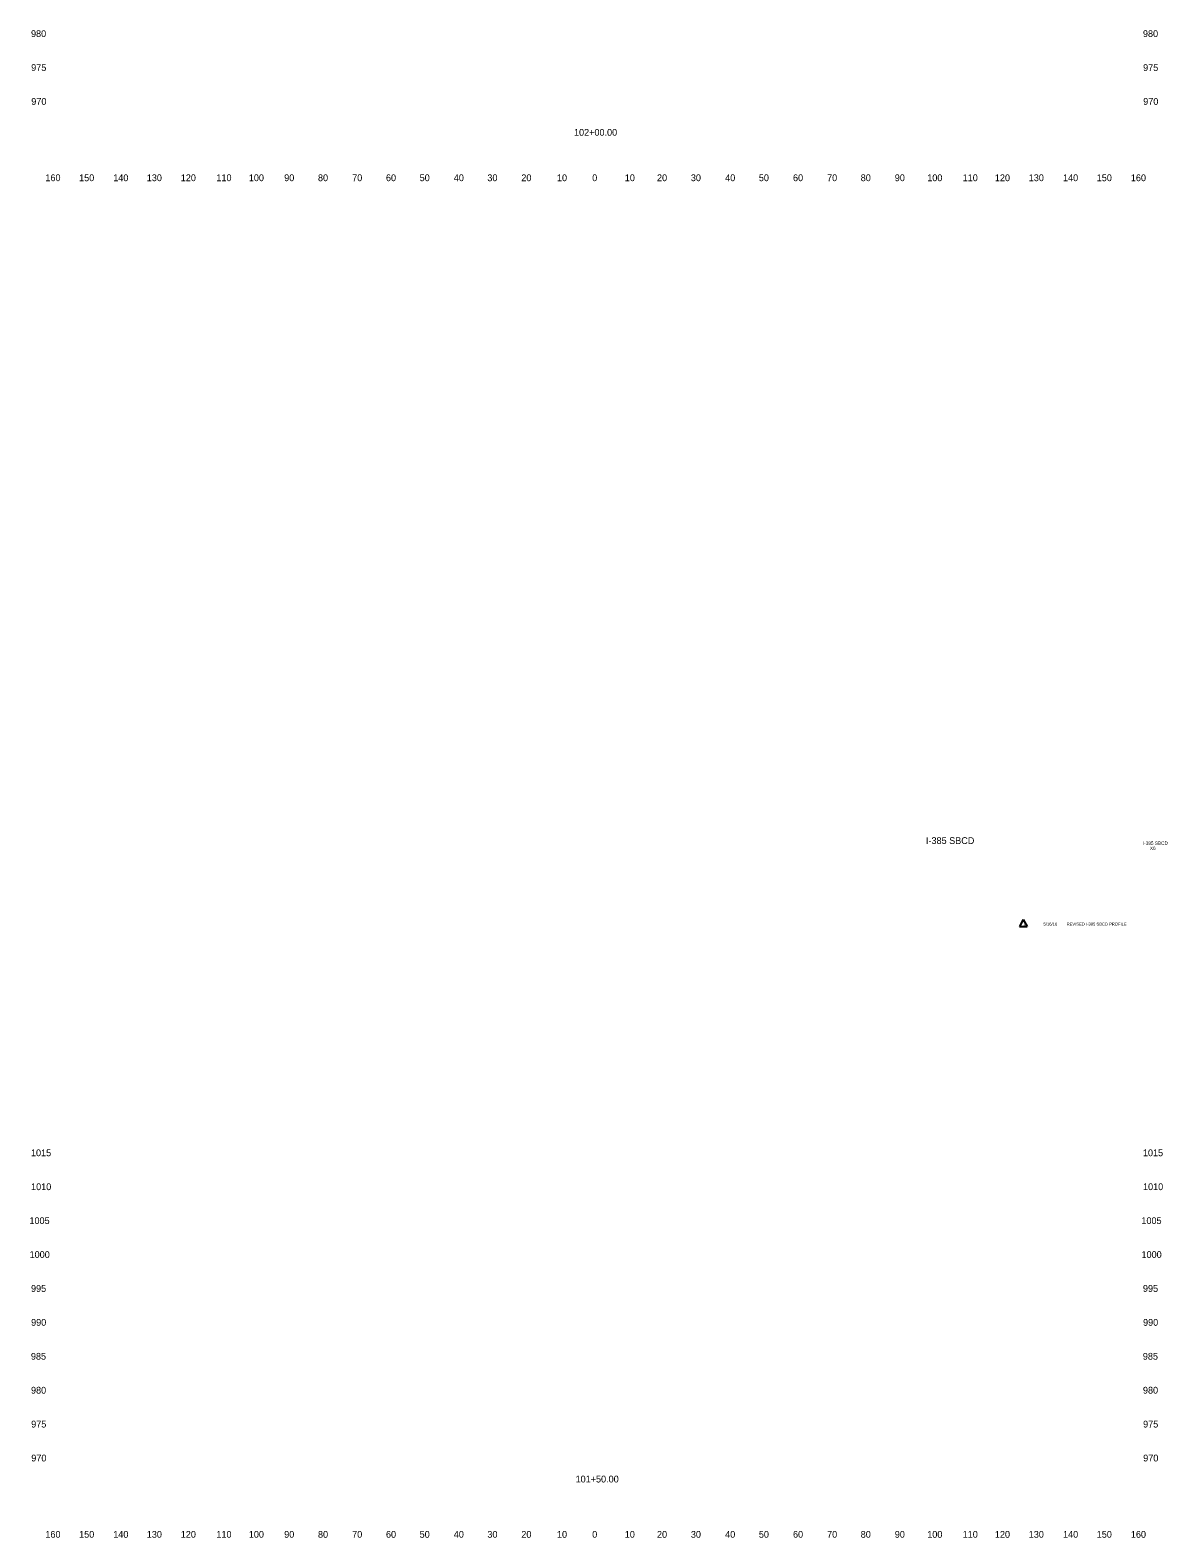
# Model space of a CAD drawing. Extents: x 4994 to 6876, y 4997 to 8804.
# Drawn here: x 4993.6 to 5328.7, y 6997.5 to 7442 of the extents above; entities that cross this region are included whole.
import ezdxf

# ---------------------------------------------------------------- set-up
doc = ezdxf.new("R2010")
doc.units = 0
for name, color, linetype in [('RD_SHT_ID', 7, 'Continuous'), ('RD_SHT_TX', 7, 'Continuous'), ('RD_XS_TX_Offset', 7, 'Continuous'), ('RD_XS_TX_Station', 7, 'Continuous')]:
    doc.layers.add(name, color=color, linetype=linetype)

msp = doc.modelspace()

# ---------------------------------------------------------------- linework, layer by layer
at = {"layer": 'RD_SHT_TX'}
for p, q in [((5286.37, 7179.75), (5285.23, 7177.72)), ((5286.37, 7179.75), (5287.51, 7177.72)), ((5285.23, 7177.72), (5287.51, 7177.72))]:
    msp.add_line(p, q, dxfattribs=at)

# ---------------------------------------------------------------- texts
at = {"layer": 'RD_SHT_ID'}
for s, height, p in [('I-385 SBCD', 2, (5257.69, 7202.06)), ('I-385 SBCD', 1, (5321.63, 7201.8)), ('X6', 1, (5323.71, 7200.3))]:
    msp.add_text(s, height=height, dxfattribs=at).set_placement(p)
at = {"layer": 'RD_SHT_TX'}
for s, p in [('1', (5286.37, 7178.05)), ('5/16/16', (5292.34, 7178.01)), ('REVISED I-385 SBCD PROFILE', (5299.17, 7178.01))]:
    msp.add_text(s, height=0.88, dxfattribs=at).set_placement(p)
at = {"layer": 'RD_XS_TX_Offset'}
for s, p in [('980', (4993.86, 7440)), ('980', (5321.66, 7440)), ('975', (4993.91, 7430)), ('975', (5321.71, 7430)), ('970', (4993.94, 7420)), ('970', (5321.74, 7420)), ('160', (4998.1, 7397.5)), ('150', (5008.04, 7397.5)), ('140', (5018.1, 7397.5)), ('130', (5027.99, 7397.5)), ('120', (5038.01, 7397.5)), ('110', (5048.51, 7397.5)), ('100', (5058.07, 7397.5)), ('90', (5068.5, 7397.5)), ('80', (5078.46, 7397.5)), ('70', (5088.54, 7397.5)), ('60', (5098.5, 7397.5)), ('50', (5108.43, 7397.5)), ('40', (5118.5, 7397.5)), ('30', (5128.39, 7397.5)), ('20', (5138.4, 7397.5)), ('10', (5148.91, 7397.5)), ('0', (5159.3, 7397.5)), ('0', (5159.3, 7397.5)), ('10', (5168.91, 7397.5)), ('20', (5178.4, 7397.5)), ('30', (5188.39, 7397.5)), ('40', (5198.5, 7397.5)), ('50', (5208.43, 7397.5)), ('60', (5218.5, 7397.5)), ('70', (5228.54, 7397.5)), ('80', (5238.46, 7397.5)), ('90', (5248.5, 7397.5)), ('100', (5258.07, 7397.5)), ('110', (5268.51, 7397.5)), ('120', (5278.01, 7397.5)), ('130', (5287.99, 7397.5)), ('140', (5298.1, 7397.5)), ('150', (5308.04, 7397.5)), ('160', (5318.1, 7397.5)), ('1015', (4993.85, 7110)), ('1015', (5321.65, 7110)), ('1010', (4993.88, 7100)), ('1010', (5321.68, 7100)), ('1005', (4993.4, 7090)), ('1005', (5321.2, 7090)), ('1000', (4993.44, 7080)), ('1000', (5321.24, 7080)), ('995', (4993.86, 7070)), ('995', (5321.66, 7070)), ('990', (4993.89, 7060)), ('990', (5321.69, 7060)), ('985', (4993.83, 7050)), ('985', (5321.63, 7050)), ('980', (4993.86, 7040)), ('980', (5321.66, 7040)), ('975', (4993.91, 7030)), ('975', (5321.71, 7030)), ('970', (4993.94, 7020)), ('970', (5321.74, 7020)), ('160', (4998.1, 6997.5)), ('150', (5008.04, 6997.5)), ('140', (5018.1, 6997.5)), ('130', (5027.99, 6997.5)), ('120', (5038.01, 6997.5)), ('110', (5048.51, 6997.5)), ('100', (5058.07, 6997.5)), ('90', (5068.5, 6997.5)), ('80', (5078.46, 6997.5)), ('70', (5088.54, 6997.5)), ('60', (5098.5, 6997.5)), ('50', (5108.43, 6997.5)), ('40', (5118.5, 6997.5)), ('30', (5128.39, 6997.5)), ('20', (5138.4, 6997.5)), ('10', (5148.91, 6997.5)), ('0', (5159.3, 6997.5)), ('0', (5159.3, 6997.5)), ('10', (5168.91, 6997.5)), ('20', (5178.4, 6997.5)), ('30', (5188.39, 6997.5)), ('40', (5198.5, 6997.5)), ('50', (5208.43, 6997.5)), ('60', (5218.5, 6997.5)), ('70', (5228.54, 6997.5)), ('80', (5238.46, 6997.5)), ('90', (5248.5, 6997.5)), ('100', (5258.07, 6997.5)), ('110', (5268.51, 6997.5)), ('120', (5278.01, 6997.5)), ('130', (5287.99, 6997.5)), ('140', (5298.1, 6997.5)), ('150', (5308.04, 6997.5)), ('160', (5318.1, 6997.5))]:
    msp.add_text(s, height=2, dxfattribs=at).set_placement(p)
at = {"layer": 'RD_XS_TX_Station'}
for s, p in [('102+00.00', (5153.93, 7410.9)), ('101+50.00', (5154.4, 7013.8))]:
    msp.add_text(s, height=2, dxfattribs=at).set_placement(p)

doc.saveas('drawing.dxf')
